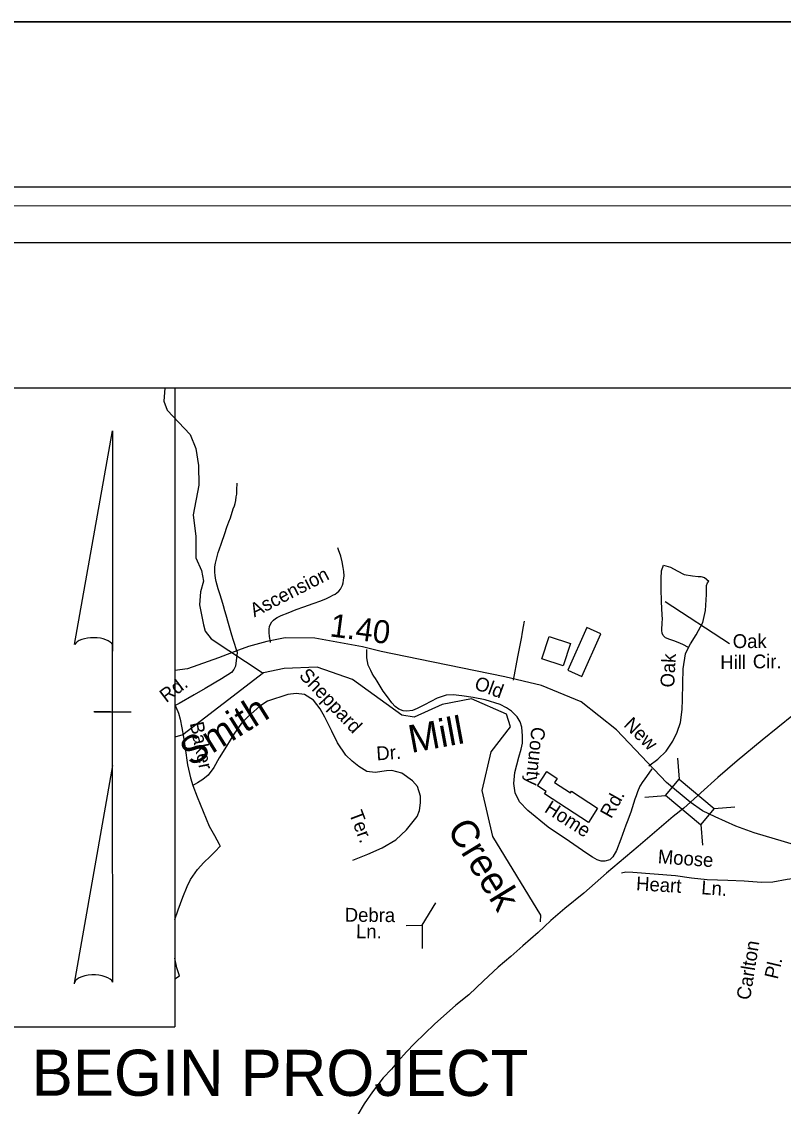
# Model space of a CAD drawing. Extents: x 925297 to 940193, y 663541 to 689899.
# Drawn here: x 927164 to 927990, y 688722 to 689899 of the extents above; entities that cross this region are included whole.
import ezdxf

# ---------------------------------------------------------------- set-up
doc = ezdxf.new("R2010")
doc.units = 0
for name, color, linetype in [('Default', 7, 'Continuous'), ('Exist Horizontal Alignment Tick Large', 7, 'Continuous'), ('Prop North Arrow for Plan Sheets CELL', 7, 'Continuous'), ('Sheet Cutting Line CELL', 7, 'Continuous'), ('Sheet Plot Border Inside CELL', 7, 'Continuous'), ('Sheet Plot Border Outside CELL', 7, 'Continuous'), ('Sheet Title CELL', 7, 'Continuous')]:
    doc.layers.add(name, color=color, linetype=linetype)

# ---------------------------------------------------------------- blocks, each defined once
blk = doc.blocks.new('North Arrow for Plan Sheets-E')
at = {"layer": 'Prop North Arrow for Plan Sheets CELL'}
for p, q in [((-0.1659, 0.293), (-0.0019, 1.22)), ((-0.0009, 1.22), (-0.0019, 1.22)), ((-0.0009, 1.22), (-0.0019, 1.22)), ((-0.0009, 1.22), (-0.0009, 0.264)), ((-0.0009, -0.232), (-0.0009, 0.292)), ((-0.0009, 0.264), (-0.0009, 0.291)), ((-0.0809, 0), (-0.0819, 0)), ((-0.0099, 0), (-0.0809, 0)), ((-0.0799, 0), (0.0801, 0)), ((-0.0009, -0.232), (-0.1679, -1.177)), ((0.0001, -1.173), (-0.0009, -0.232))]:
    blk.add_line(p, q, dxfattribs=at)
for centre, start_param, end_param in [((-0.0832, 0.2831), 0.216388, 2.908219), ((-0.0832, -1.1803), 0.201328, 3.141593)]:
    blk.add_ellipse(centre, major_axis=(0.0846, -0.0006), ratio=0.461098, start_param=start_param, end_param=end_param, dxfattribs=at)

msp = doc.modelspace()

# ---------------------------------------------------------------- linework, layer by layer
at = {"layer": 'Default'}
for p, q in [((927874.9, 689099.5), (927876.9, 689076.9)), ((927839.4, 689057.3), (927861.9, 689059.2)), ((927914.7, 689044.9), (927937.3, 689046.9)), ((927900.2, 689027.6), (927902.1, 689005.1))]:
    msp.add_line(p, q, dxfattribs=at)
for points in [[(927319.1, 689501.3), (927319, 689501.1), (927317.7, 689486.8), (927321.3, 689477), (927346.4, 689450.9), (927352.7, 689435.5), (927355.6, 689417.3), (927355.7, 689395.7), (927349.7, 689363.5), (927352.5, 689340.2), (927352.4, 689317), (927358.7, 689303.2), (927360.7, 689291.5), (927357.5, 689280), (927356.6, 689266), (927361, 689244.2), (927362.8, 689237.4), (927369.3, 689229.1), (927425.7, 689192)], [(927397.3, 689214.9), (927393.3, 689227.3), (927391.7, 689233), (927387.8, 689245.6), (927385.5, 689254.7), (927384.1, 689259.6), (927382.5, 689264.8), (927380.7, 689270.9), (927378.5, 689278), (927376.7, 689283.3), (927375.5, 689287.5), (927374.7, 689291.4), (927373.9, 689294.8), (927373.4, 689298.1), (927373.2, 689301), (927373.1, 689304.7), (927373.3, 689307.3), (927373.8, 689311.3), (927374.6, 689314.1), (927375.5, 689318.6), (927376.6, 689322.7), (927378, 689325.8), (927380.2, 689332.8), (927384.1, 689343.2), (927386.2, 689350.3), (927388.4, 689356), (927390.1, 689360.2), (927393.1, 689370.1), (927394.3, 689373.3), (927395.1, 689376), (927395.8, 689379.2), (927396.3, 689383), (927396.9, 689386.2), (927397.1, 689390.6), (927397.4, 689398.1)], [(927433.5, 689225.2), (927433.4, 689225.8), (927432.6, 689231.5), (927432.1, 689236.1), (927432.1, 689239.7), (927432.6, 689242.5), (927433.5, 689245.1), (927434.8, 689247.5), (927436.8, 689249.5), (927438.9, 689251), (927440.9, 689252.3), (927445.1, 689254.5), (927452.6, 689257.4), (927461.5, 689260.8), (927469.7, 689263.8), (927479.7, 689267.4), (927488, 689270.5), (927494.3, 689273), (927498.6, 689274.9), (927501.3, 689276.3), (927503.7, 689277.5), (927505.6, 689279), (927507.5, 689280.9), (927509.3, 689283), (927510.6, 689285.3), (927511.6, 689287.5), (927512.4, 689290), (927512.8, 689292.7), (927513.6, 689297.5), (927513.1, 689302.2), (927512.4, 689306.6), (927511.2, 689312.8), (927509.8, 689318.7), (927507.1, 689325.7), (927506.6, 689327.8)], [(927887.1, 689219.8), (927880.6, 689223.1), (927878.3, 689224.1), (927872, 689226.6), (927866.6, 689228.4), (927862, 689230.3), (927859.4, 689232.6), (927858.3, 689235.2), (927858, 689238.2), (927858.4, 689247.1), (927858.7, 689250.1), (927857.9, 689261.4), (927857.7, 689270.3), (927857.4, 689282.8), (927857.2, 689294.4), (927857.5, 689302.9), (927859.7, 689309.1), (927867.3, 689307), (927874.7, 689302.9), (927882.2, 689298.9), (927891.3, 689297.3), (927897.5, 689296.8), (927900.4, 689296.6), (927904.2, 689295.5), (927909.1, 689291.8)], [(927887.1, 689219.8), (927889, 689223.5), (927895.2, 689233.4), (927902.4, 689246.8), (927905.5, 689259.8), (927906.3, 689277.1), (927906.3, 689287), (927907.4, 689290), (927909.1, 689291.8)], [(927931.3, 689223.5), (927861.6, 689269.3)], [(927697, 689184.1), (927701.9, 689209.7), (927706, 689231.1), (927706.6, 689234), (927708, 689242.4), (927709.2, 689248.3)], [(927888.8, 689051.9), (927862.9, 689073.4), (927808.8, 689130.5), (927770.5, 689160.9), (927727.6, 689178.5), (927687.7, 689187.7), (927594.2, 689207.1), (927553.5, 689215.4), (927533.2, 689220.3), (927481.7, 689229.9), (927449.5, 689230.3), (927429.6, 689226.1), (927409.7, 689220.8), (927398.7, 689216.7), (927377, 689208.6), (927343.5, 689196.7), (927329.6, 689194.6)], [(927843.9, 689091.2), (927853.7, 689098.5), (927862.6, 689107.2), (927869.8, 689118), (927874.8, 689127.9), (927878.1, 689138.3), (927880.2, 689152.6), (927880.5, 689163.3), (927880.9, 689180.7), (927881.2, 689196.5), (927883.6, 689212.7), (927887.1, 689219.8)], [(927397.3, 689214.9), (927397.5, 689214.2), (927395.4, 689199.4), (927395.1, 689198.6), (927393.7, 689195.8), (927391.1, 689192.7), (927380.5, 689185.7), (927362.5, 689175.2), (927350.6, 689168.4), (927334.4, 689159), (927330.1, 689156.6)], [(927706.9, 689123.4), (927706.9, 689123.7), (927706, 689133.1), (927704.2, 689138.9), (927701, 689144.5), (927694.8, 689150.6), (927689.6, 689154.2), (927682.8, 689157.7), (927666.2, 689162.8), (927653.4, 689165.3), (927641.2, 689167.4), (927631.6, 689168.3), (927624.1, 689167.9), (927614.2, 689164.8), (927600.4, 689157.6), (927592.5, 689153.4), (927587.5, 689151.5), (927581.3, 689150.6), (927577.4, 689151), (927572.8, 689152.8), (927568.9, 689155.6), (927565, 689159.6), (927560.5, 689166), (927555.9, 689172.2), (927549.2, 689183.2), (927547.3, 689185.9), (927545.5, 689188.7), (927543.8, 689191.6), (927542.3, 689194.6), (927540.8, 689197.6), (927539.6, 689200.7), (927537.9, 689208.4), (927538.1, 689217.6)], [(927726.4, 688922.2), (927726.6, 688929.4), (927674.6, 689014.5), (927663.1, 689064.6), (927672.9, 689106.4), (927693.9, 689133.5), (927689.4, 689147.4), (927651.6, 689163.9), (927619.7, 689158), (927589.2, 689144.2), (927576, 689146.4), (927522.5, 689185.1), (927484.1, 689198.2), (927448.3, 689196.9), (927425.8, 689192.1), (927338.3, 689124.8), (927329.6, 689122.6)], [(927522.7, 688989), (927526.5, 688990.4), (927539.1, 688995.5), (927554.8, 689002.5), (927569.5, 689011), (927581, 689021.9), (927592.7, 689036.4), (927595.1, 689042.8), (927596.4, 689051.1), (927596.1, 689058.4), (927592.9, 689068.9), (927587.4, 689075.2), (927576.1, 689083.2), (927565.1, 689086.2), (927559.2, 689086), (927547.2, 689084.2), (927538.1, 689085.2), (927529.2, 689090.6), (927522, 689096.5), (927515.4, 689102.9), (927506.1, 689116.1), (927500.1, 689129.1), (927492.6, 689144.1), (927487.5, 689153), (927480.2, 689162.6), (927470.4, 689168.7), (927461.3, 689169.8), (927452.3, 689168.8), (927430.1, 689161.5), (927421.9, 689156.1), (927408.8, 689144.5), (927401.9, 689137.6), (927393.8, 689125.8), (927385.8, 689112.5), (927378, 689099.9), (927371.9, 689089.6), (927365.8, 689081.1), (927360, 689076.6), (927354.5, 689072.7), (927349.3, 689070)], [(927330.1, 689156.6), (927329.6, 689156.3)], [(927330.1, 689156.6), (927333, 689150.3), (927333.9, 689148.4), (927335.5, 689141.8), (927337.3, 689132.7), (927339.2, 689122.3), (927341.1, 689110.5), (927343.6, 689092.5), (927346.9, 689078.2), (927349.3, 689070)], [(928000.7, 689146.8), (927966.9, 689119.2), (927939.7, 689096.6), (927918.7, 689078.6), (927881.9, 689045.5), (927870.3, 689036.3), (927832.3, 689003.7), (927798.1, 688975), (927773.3, 688953.2), (927752.7, 688936.5), (927737.7, 688923.7), (927723.7, 688910.6), (927707.1, 688895.9), (927694.3, 688884.4), (927680.3, 688872.9), (927664.5, 688858.2), (927648.5, 688842.8), (927634.5, 688831.8), (927611.3, 688811.2), (927600.9, 688800.9), (927589.7, 688790.1), (927580.9, 688780.9), (927572.1, 688770.8), (927564.7, 688762.3), (927555.9, 688752.7), (927544.1, 688737.5), (927535.3, 688724.5), (927528.1, 688713.1)], [(927820.4, 689030.7), (927819.1, 689027.1), (927813.7, 689011.6), (927808.8, 688999.3), (927804.9, 688992.7), (927801.6, 688989.3), (927796.2, 688987.8), (927792.2, 688988), (927787.8, 688989.5), (927782.8, 688992.1), (927776.6, 688996.1), (927757.7, 689009.3), (927734.8, 689024.7), (927712.5, 689042.7), (927703.7, 689052.4), (927698.9, 689062.1), (927697.5, 689072.3), (927698.7, 689084.2), (927702.9, 689100.8), (927705.3, 689109.3), (927706.8, 689115.8), (927706.9, 689123.4)], [(927847.2, 689088), (927838.7, 689076.3), (927837.3, 689074.3), (927834.3, 689069.3), (927831.7, 689063), (927830, 689058.6)], [(927349.3, 689070), (927354, 689057.6), (927367, 689026), (927372.9, 689015.7), (927377.8, 689006.4), (927379, 689004.3)], [(927830, 689058.6), (927828.8, 689055.2), (927824.2, 689040.9), (927820.4, 689030.7)], [(928236.9, 688765.2), (928232.1, 688781), (928230.7, 688788), (928218.8, 688831.2), (928212.3, 688851.5), (928200.1, 688880.1), (928194, 688891.3), (928170, 688925.1), (928135.6, 688955.1), (928101.1, 688974.7), (928070.5, 688986.2), (928023.9, 688999.1), (927958.2, 689018.8), (927938.3, 689025.8), (927916, 689035.9), (927902.2, 689042.5), (927888.8, 689051.9)], [(927329.6, 688924.7), (927329.7, 688924.7), (927333.2, 688935.1), (927338.4, 688948.9), (927343.3, 688960.4), (927346.9, 688968), (927354.2, 688979), (927361.2, 688986.5), (927368, 688992.8), (927373.8, 688998.8), (927378.4, 689003.7), (927379, 689004.3)], [(928100.9, 688972.2), (928096, 688964), (928092.6, 688961.1), (928086.4, 688960.2), (928081.9, 688961.3), (928072.4, 688965.2), (928064.5, 688968.3), (928056.2, 688971.3), (928040.9, 688975.8), (928029.5, 688975.4), (928019.2, 688973.8), (927999.7, 688968.9), (927994, 688967.9), (927978.5, 688965.2), (927966, 688964.6), (927947.3, 688966.1), (927929.6, 688966.8), (927907.1, 688967.8), (927890.3, 688969.3), (927872.9, 688972), (927826.6, 688975.7), (927819, 688976.1), (927814.3, 688975)], [(927598.2, 688918.6), (927612.8, 688942.8)], [(927580.5, 688918), (927598.2, 688918.6), (927598.2, 688893.2)], [(927334.7, 688863.6), (927331.9, 688872), (927329.6, 688882.7)], [(927329.6, 688860.1), (927334.7, 688863.6)]]:
    msp.add_lwpolyline(points, dxfattribs=at)
for points in [[(927759.1, 689224.1), (927751, 689199.8), (927727.9, 689207.5), (927735.9, 689231.8)], [(927771.4, 689188.4), (927791.9, 689234.5), (927776.5, 689241.4), (927756, 689195.2)], [(927778.3, 689030), (927730.8, 689060.9), (927732.4, 689063.5), (927723.1, 689069.6), (927733.1, 689085.1), (927744.4, 689077.7), (927741.6, 689073.4), (927758.9, 689062.2), (927759.9, 689063.7), (927788.3, 689045.3)], [(927876.9, 689076.9), (927914.8, 689045), (927899.9, 689027.3), (927861.9, 689059.2)]]:
    msp.add_lwpolyline(points, close=True, dxfattribs=at)
at = {"layer": 'Sheet Cutting Line CELL'}
msp.add_line((925296.7, 689898.6), (938768.7, 689898.6), dxfattribs=at)
at = {"layer": 'Sheet Plot Border Inside CELL'}
msp.add_lwpolyline([(925400.7, 681278.2), (938732.7, 681278.2), (938732.7, 689719), (925400.7, 689719)], close=True, dxfattribs=at)
at = {"layer": 'Sheet Plot Border Outside CELL'}
msp.add_lwpolyline([(938768.7, 689898.6), (925296.7, 689898.6), (925296.7, 681098.7), (938768.7, 681098.7)], close=True, dxfattribs=at)
at = {"layer": 'Sheet Title CELL'}
for p in [(927329.6, 689501.3), (927148.4, 688808.3)]:
    msp.add_line(p, (927329.6, 688808.3), dxfattribs=at)
for points in [[(938552.8, 689698.6), (926712.6, 689698.7)], [(938512.7, 689658.6), (927152.8, 689658.6)]]:
    msp.add_lwpolyline(points, dxfattribs=at)
msp.add_lwpolyline([(927148.4, 689501.3), (930192.1, 689501.3), (930192.1, 687400.3), (927148.4, 687400.3)], close=True, dxfattribs=at)

# ---------------------------------------------------------------- block references
at = {"layer": 'Exist Horizontal Alignment Tick Large', "xscale": 250.00000000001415, "yscale": 250.00000000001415, "rotation": 1.0523656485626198e-11}
msp.add_blockref('North Arrow for Plan Sheets-E', (927262.5, 689149.8), dxfattribs=at)

# ---------------------------------------------------------------- texts
at = {"layer": 'Default'}
for s, height, rotation, p in [('Ascension', 15, 26.9662, (927416, 689252.2)), ('1.40', 25, 352.3759, (927497.1, 689231.9)), ('Oak', 15, 86.9405, (927871.3, 689176)), ('Sheppard', 15, 313.3166, (927463.6, 689188.6)), ('Rd.', 15, 37.098, (927320.4, 689159.2)), ('Old', 15, 339.9799, (927653.6, 689175)), ('Smith', 30, 31.9599, (927347.5, 689090)), ('Baker', 15, 281.7729, (927345.9, 689137.5)), ('Mill', 30, 10.5218, (927586.1, 689105.2)), ('New', 15, 315.846, (927815.7, 689134.8)), ('County', 15, 264.0284, (927716.8, 689134.1)), ('Dr.', 15, 3.8049, (927548.8, 689097.2)), ('Rd.', 15, 60.6528, (927803.1, 689033.2)), ('Ter.', 15, 290.7748, (927518.5, 689039.6)), ('Home', 15, 327.2958, (927729.6, 689041.9)), ('Creek', 30, 301.4338, (927624.3, 689022.6)), ('Moose', 15, 355.9749, (927853.3, 688985.6)), ('Heart', 15, 356.6867, (927829.8, 688956.3)), ('Ln.', 15, 355.8426, (927900.4, 688952.1)), ('Debra', 15, 359.4318, (927514, 688922.3)), ('Ln.', 15, 359.3781, (927526.2, 688904.3)), ('Carlton', 15, 80.8396, (927953.6, 688836.6)), ('Pl.', 15, 76.7671, (927983.6, 688859.1))]:
    msp.add_text(s, height=height, rotation=rotation, dxfattribs=at).set_placement(p)
for s, p in [('Oak', (927934.9, 689219.1)), ('Hill', (927921.4, 689196.2)), ('Cir.', (927956.7, 689197.1))]:
    msp.add_text(s, height=15, dxfattribs=at).set_placement(p)
at = {"layer": 'Exist Horizontal Alignment Tick Large'}
msp.add_text('BEGIN PROJECT ', height=50, rotation=359.9706, dxfattribs=at).set_placement((927174.5, 688733.4))

doc.saveas('drawing.dxf')
